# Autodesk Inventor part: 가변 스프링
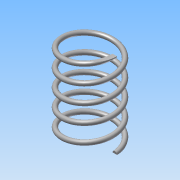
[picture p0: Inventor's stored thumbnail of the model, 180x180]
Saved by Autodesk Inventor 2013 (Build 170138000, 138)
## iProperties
Created: 2015-10
Part Number: 가변 스프링
Material: 강철, 연강
Document SubType Name: Modeling
Designer: Administrator
Density: 7.86 g/cm^3
Mass: 1.05471 g
Surface Area: 5.42544 cm^2
Volume: 0.134186 cm^3
Author: Administrator
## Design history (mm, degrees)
sketch "스케치1"
  geometry: L1 (0, 0)-(5.5, 0); L2 (5.5, 0)-(5.5, 18.948); L3 (5.5, 18.948)-(0, 18.948); L4 (0, 18.948)-(0, 0); C1 r 0.5 at (5.5, 0)
  constraints: 8 end point, 2 parallel, 1 centre point, 1 coincident, 1 horizontal, 1 perpendicular
  dimensions: "d0" = 11 diameter of L2 L4; "d2" = 18.94782 distance of L1.end L2.end (derived); "d3" = 1 diameter of C1
feature "코일1" sketch "스케치1" pitch "d4" = 10; turns "d6" = 5; dims "d5" = 18.94782 (= d2), "d7" = 0, angle "d8" = 90 deg, angle "d9" = 90 deg, "d10" = 0, "d11" = 0
node "작업 평면1"
feature "분할1"
node "작업 평면2"
feature "분할2"
node "솔리드1"
other parameters: "d12" = 90 deg, "d13" = 90 deg
